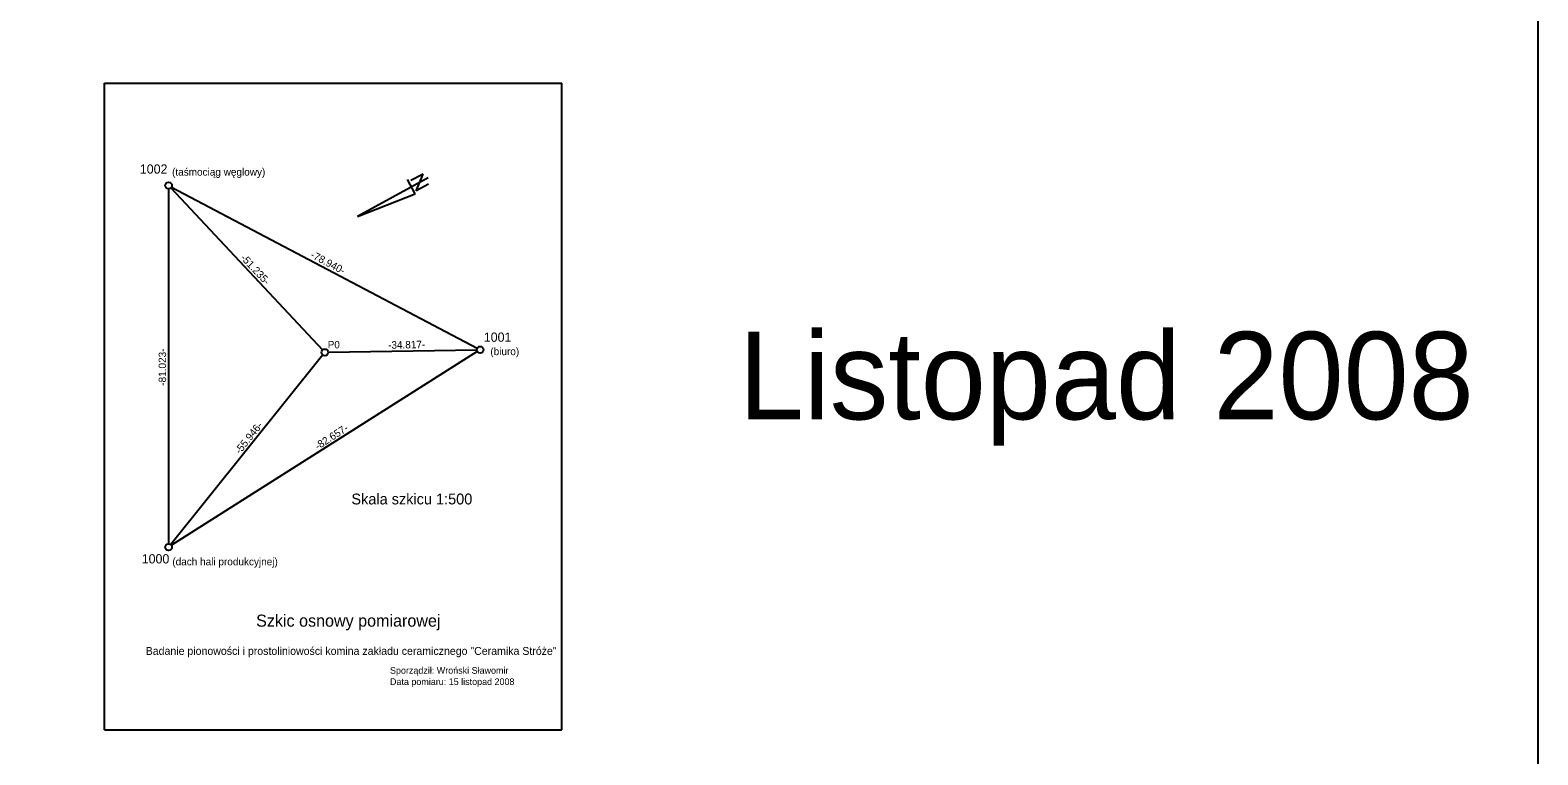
# Model space of a CAD drawing. Extents: x 138 to 264, y -75 to 121.
# Drawn here: x 195.1 to 264.4, y -31.7 to 1.6 of the extents above; entities that cross this region are included whole.
import ezdxf

# ---------------------------------------------------------------- set-up
doc = ezdxf.new("R2010")
doc.units = 0
for name, color, linetype in [('15 listopad 2008', 7, 'Continuous'), ('Default', 7, 'Continuous'), ('Opisy', 7, 'Continuous'), ('Ramka do drukowania', 7, 'Continuous'), ('Standard', 7, 'Continuous')]:
    doc.layers.add(name, color=color, linetype=linetype)

msp = doc.modelspace()

# ---------------------------------------------------------------- linework, layer by layer
at = {"layer": '15 listopad 2008'}
msp.add_lwpolyline([(137.936, 38.661), (264.389, 38.661), (264.389, -75.347), (137.936, -75.347)], close=True, dxfattribs=at)
at = {"layer": 'Ramka do drukowania'}
for p, q in [((198.566, -30.544), (198.566, -0.844)), ((198.566, -0.844), (219.566, -0.844)), ((219.566, -30.544), (219.566, -0.844)), ((198.566, -30.544), (219.566, -30.544))]:
    msp.add_line(p, q, dxfattribs=at)
at = {"layer": 'Standard'}
for p, q in [((213.429, -5.195), (210.173, -6.976)), ((212.829, -5.931), (212.481, -5.273)), ((213.19, -5.027), (212.633, -5.324)), ((212.88, -5.787), (213.19, -5.027)), ((213.437, -5.49), (212.88, -5.787)), ((201.503, -5.547), (201.503, -5.547)), ((201.503, -5.701), (201.503, -10.563)), ((201.608, -5.659), (208.573, -13.097)), ((201.639, -5.619), (215.675, -13.017)), ((210.173, -6.976), (212.829, -5.931)), ((201.503, -10.563), (201.503, -12.043)), ((201.503, -12.043), (201.503, -21.994)), ((208.832, -13.207), (215.657, -13.091)), ((215.811, -13.088), (215.811, -13.088)), ((208.582, -13.329), (201.599, -22.028)), ((215.681, -13.171), (201.632, -22.066)), ((201.503, -22.148), (201.503, -22.148))]:
    msp.add_line(p, q, dxfattribs=at)
for centre in [(201.503, -5.547), (208.679, -13.209), (215.811, -13.088), (201.503, -22.148)]:
    msp.add_circle(centre, 0.154, dxfattribs=at)

# ---------------------------------------------------------------- texts
at = {"layer": 'Default'}
msp.add_text('Listopad 2008', height=4.01714, dxfattribs=at).set_placement((227.691, -16.283))
at = {"layer": 'Opisy'}
msp.add_text('Data pomiaru: 15 listopad 2008', height=0.30766, dxfattribs=at).set_placement((211.671, -28.48))
at = {"layer": 'Standard'}
for s, height, p in [('1002', 0.426, (200.184, -5.006)), ('(taśmociąg węglowy)', 0.34308, (201.663, -5.097)), ('1001', 0.426, (215.981, -12.724)), ('P0', 0.3382, (208.814, -13.022)), ('(biuro)', 0.3431, (216.281, -13.337)), ('Skala szkicu 1:500', 0.49797, (209.9, -20.189)), ('1000', 0.426, (200.27, -22.899)), ('(dach hali produkcyjnej)', 0.34308, (201.675, -22.986)), ('Szkic osnowy pomiarowej', 0.55314, (205.523, -25.801)), ('Badanie pionowości i prostoliniowości komina zakładu ceramicznego "Ceramika Stróże"', 0.36281, (200.453, -27.096)), ('Sporządził: Wroński Sławomir', 0.30766, (211.671, -27.963))]:
    msp.add_text(s, height=height, dxfattribs=at).set_placement(p)
for s, rotation, p in [('-51.235-', 313.18745, (204.781, -8.894)), ('-78.940-', 332.12805, (207.99, -8.838)), ('-81.023-', 90, (201.389, -14.741)), ('-34.817-', 1.09229, (211.586, -13.045)), ('-55.946-', 51.39237, (204.78, -17.908)), ('-82.657-', 32.82854, (208.359, -17.697))]:
    msp.add_text(s, height=0.3431, rotation=rotation, dxfattribs=at).set_placement(p)

doc.saveas('drawing.dxf')
